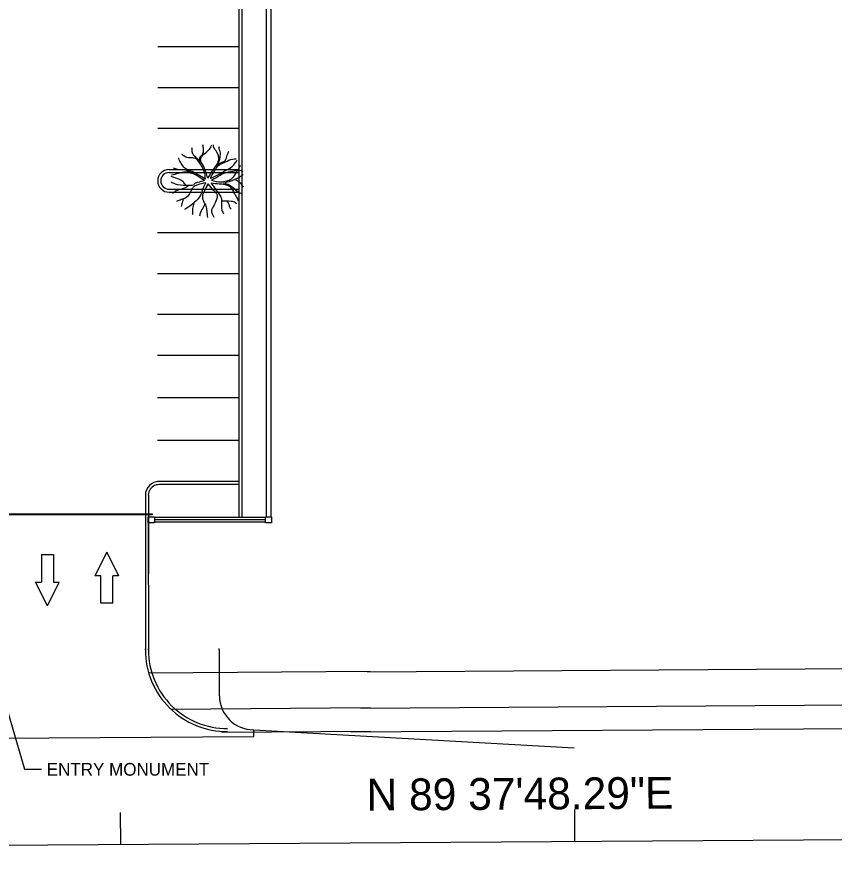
# Model space of a CAD drawing. Extents: x 6711323 to 6714641, y 1869258 to 1871224.
# Drawn here: x 6713129 to 6713309, y 1869589.4 to 1869774.5 of the extents above; entities that cross this region are included whole.
import ezdxf

# ---------------------------------------------------------------- set-up
doc = ezdxf.new("R2010")
doc.units = 0
for name, color, linetype in [('49 Planting', 7, 'Continuous'), ('Curb Gutter (21)', 7, 'Continuous'), ('Exist Utils (5)', 7, 'Continuous'), ('Front Align (17)', 7, 'Continuous'), ('Level 11', 7, 'Continuous'), ('Level 13', 7, 'Continuous'), ('Level 14', 7, 'Continuous'), ('Level 21', 7, 'Continuous'), ('Level 46', 7, 'Continuous'), ('Level 60', 7, 'Continuous'), ('Misc CnstDet(22)', 7, 'Continuous'), ('Nongeo Data(60)', 7, 'Continuous'), ('Profile Grid (9)', 7, 'Continuous'), ('Undefined (Lv19)', 7, 'Continuous'), ('Undefined (Lv26)', 7, 'Continuous')]:
    doc.layers.add(name, color=color, linetype=linetype)

msp = doc.modelspace()

# ---------------------------------------------------------------- linework, layer by layer
at = {"layer": '49 Planting'}
for p, q in [((6713122.22, 1869637.78), (6713130.69, 1869608.81)), ((6713130.69, 1869608.81), (6713134.46, 1869608.82))]:
    msp.add_line(p, q, dxfattribs=at)
at = {"layer": 'Curb Gutter (21)'}
for p, q in [((6713177.99, 1869664.24), (6713177.99, 1869903.09)), ((6713178.66, 1869664.24), (6713178.66, 1869903.12)), ((6713162.53, 1869740.86), (6713177.99, 1869740.86)), ((6713162.53, 1869735.86), (6713177.99, 1869735.86)), ((6713177.99, 1869672.16), (6713160.31, 1869672.16)), ((6713157.31, 1869663.67), (6713157.31, 1869635.09)), ((6713157.96, 1869663.72), (6713157.98, 1869635.09))]:
    msp.add_line(p, q, dxfattribs=at)
for centre, radius, end in [((6713162.53, 1869738.36), 2.5, 270), ((6713160.31, 1869669.16), 3, 180)]:
    msp.add_arc(centre, radius, 90, end, dxfattribs=at)
at = {"layer": 'Exist Utils (5)'}
msp.add_line((6713157.31, 1869669.19), (6713157.31, 1869651.86), dxfattribs=at)
at = {"layer": 'Front Align (17)'}
for p, q in [((6713178.03, 1869767.86), (6713160.03, 1869767.86)), ((6713178.03, 1869758.86), (6713160.03, 1869758.86)), ((6713178.03, 1869749.86), (6713160.03, 1869749.86)), ((6713177.99, 1869726.9), (6713159.99, 1869726.9)), ((6713177.99, 1869717.9), (6713159.99, 1869717.9)), ((6713177.99, 1869708.9), (6713159.99, 1869708.9)), ((6713177.99, 1869699.9), (6713159.99, 1869699.9)), ((6713177.99, 1869690.62), (6713159.99, 1869690.62)), ((6713177.99, 1869681.16), (6713159.99, 1869681.16)), ((6713177.99, 1869681.16), (6713159.99, 1869681.16)), ((6713177.99, 1869672.16), (6713159.99, 1869672.16))]:
    msp.add_line(p, q, dxfattribs=at)
at = {"layer": 'Level 11'}
for p, q in [((6713173.56, 1869635.09), (6713173.56, 1869624.94)), ((6713181.16, 1869617.49), (6713251.7, 1869613.53)), ((6713181.17, 1869615.99), (6713181.16, 1869617.49)), ((6712948.69, 1869614.49), (6713181.17, 1869615.99))]:
    msp.add_line(p, q, dxfattribs=at)
msp.add_arc((6713181.12, 1869624.99), 7.5, 180.3699, 270.2774, dxfattribs=at)
at = {"layer": 'Level 13'}
msp.add_line((6712709.06, 1869589.44), (6713820.2, 1869596.61), dxfattribs=at)
at = {"layer": 'Level 14'}
for points in [[(6713151.79, 1869599.3), (6713151.83, 1869592.3)], [(6713251.78, 1869599.95), (6713251.83, 1869592.95)]]:
    msp.add_lwpolyline(points, dxfattribs=at)
at = {"layer": 'Level 21'}
for p, q in [((6713173.56, 1869635.09), (6713173.56, 1869624.94)), ((6713181.16, 1869617.49), (6713251.7, 1869613.53)), ((6712948.69, 1869614.49), (6713181.17, 1869615.99)), ((6712948.69, 1869614.49), (6713181.17, 1869615.99))]:
    msp.add_line(p, q, dxfattribs=at)
msp.add_arc((6713181.12, 1869624.99), 7.5, 180.3699, 270.2774, dxfattribs=at)
at = {"layer": 'Level 46'}
for p, q in [((6713157.31, 1869635.09), (6713157.31, 1869635.32)), ((6713157.98, 1869635.09), (6713157.98, 1869635.32)), ((6713173.56, 1869635.09), (6713173.56, 1869635.42)), ((6713206.25, 1869630.28), (6713790.23, 1869633.99)), ((6713158.04, 1869630.02), (6713206.81, 1869630.37)), ((6713204.75, 1869622.27), (6713790.23, 1869625.99)), ((6713162.9, 1869622.06), (6713206.87, 1869622.37)), ((6713202.57, 1869617.07), (6713790.35, 1869620.81)), ((6713174.13, 1869616.97), (6713206.9, 1869617.18))]:
    msp.add_line(p, q, dxfattribs=at)
for radius in [18, 18, 17.33]:
    msp.add_arc((6713175.31, 1869635.09), radius, 180, 270.3648, dxfattribs=at)
at = {"layer": 'Level 60'}
msp.add_line((6713181.17, 1869615.99), (6713181.16, 1869617.49), dxfattribs=at)
at = {"layer": 'Misc CnstDet(22)'}
for p in [(6713183.79, 1869663.74), (6713176.47, 1869663.74)]:
    msp.add_line(p, (6713159.3, 1869663.74), dxfattribs=at)
msp.add_lwpolyline([(6713124.96, 1869665.07), (6713158.81, 1869665.07), (6713158.81, 1869664.82), (6713124.96, 1869664.82)], close=True, dxfattribs=at)
msp.add_lwpolyline([(6713124.96, 1869665.07), (6713158.81, 1869665.07), (6713158.81, 1869664.82), (6713124.96, 1869664.82)], close=True, dxfattribs=at)
at = {"layer": 'Nongeo Data(60)'}
for p, q in [((6713183.98, 1869664.41), (6713183.98, 1869902.46)), ((6713184.98, 1869664.41), (6713184.98, 1869902.48))]:
    msp.add_line(p, q, dxfattribs=at)
at = {"layer": 'Profile Grid (9)'}
for points in [[(6713169.36, 1869742.48), (6713168.65, 1869743.32), (6713167.74, 1869744.34), (6713167.61, 1869745.24), (6713167.55, 1869745.6)], [(6713169.23, 1869742.84), (6713169.42, 1869743.62), (6713169.55, 1869743.8), (6713169.94, 1869744.28), (6713170.14, 1869745.3), (6713169.94, 1869746.32)], [(6713171.04, 1869738.94), (6713170.66, 1869740.26), (6713169.94, 1869741.88), (6713169.49, 1869742.78), (6713169.68, 1869743.68), (6713170.2, 1869744.22), (6713171.17, 1869745.06), (6713171.69, 1869745.72), (6713171.95, 1869746.26)], [(6713171.04, 1869738.94), (6713172.28, 1869740.86), (6713173.44, 1869742.84), (6713173.44, 1869743.74), (6713173.05, 1869744.7), (6713172.4, 1869745.72), (6713172.28, 1869746.26)], [(6713173.05, 1869741.7), (6713173.57, 1869742.72), (6713173.77, 1869743.56), (6713173.77, 1869744.82), (6713173.57, 1869745.54), (6713173.64, 1869745.9)], [(6713170.53, 1869738.76), (6713168.4, 1869739.98), (6713166.76, 1869740.78), (6713165.99, 1869741.17), (6713165.21, 1869742.21), (6713164.69, 1869743.25), (6713164.69, 1869743.41)], [(6713170.53, 1869738.76), (6713170.27, 1869740.44), (6713169.62, 1869741.76), (6713168.84, 1869742.84), (6713168.32, 1869743.32), (6713168, 1869743.38), (6713167.16, 1869743.44), (6713166.44, 1869743.5), (6713165.6, 1869743.98), (6713165.34, 1869744.16)], [(6713171.63, 1869738.94), (6713172.73, 1869740.92), (6713173.25, 1869741.58), (6713174.02, 1869742.12), (6713175.32, 1869742.72), (6713176.94, 1869743.2), (6713177.33, 1869743.2)], [(6713173.05, 1869741.7), (6713174.02, 1869742.42), (6713174.74, 1869742.72), (6713175.06, 1869743.14), (6713175.45, 1869744.28), (6713175.71, 1869744.88)], [(6713171.63, 1869738.94), (6713174.01, 1869740.06), (6713175.05, 1869740.7), (6713175.82, 1869741.09), (6713177.03, 1869742.21), (6713177.55, 1869742.93)], [(6713171.85, 1869738.54), (6713174.01, 1869738.14), (6713175.22, 1869738.38), (6713176.25, 1869738.78), (6713177.2, 1869739.98), (6713177.89, 1869741.09), (6713178.24, 1869741.81)], [(6713167.54, 1869739.98), (6713166.24, 1869740.3), (6713164.52, 1869739.98), (6713163.05, 1869739.58)], [(6713170.3, 1869738.46), (6713168.92, 1869739.34), (6713167.19, 1869740.3), (6713165.9, 1869740.78), (6713164.43, 1869740.85), (6713163.48, 1869741.17)], [(6713171.85, 1869738.54), (6713173.75, 1869739.58), (6713174.87, 1869740.14), (6713175.91, 1869740.38), (6713176.86, 1869740.54), (6713178.41, 1869740.62), (6713178.76, 1869740.46)], [(6713174.53, 1869737.9), (6713176.17, 1869738.38), (6713177.2, 1869738.78), (6713178.24, 1869739.34), (6713178.84, 1869739.74)], [(6713166.24, 1869737.42), (6713165.64, 1869738.14), (6713163.83, 1869739.02), (6713162.97, 1869739.34)], [(6713170.3, 1869738.46), (6713168.75, 1869737.98), (6713168.14, 1869737.74), (6713167.88, 1869737.42), (6713167.37, 1869737.34), (6713166.16, 1869737.34), (6713163.91, 1869737.66), (6713162.97, 1869738.06)], [(6713170.56, 1869737.9), (6713168.83, 1869737.5), (6713168.14, 1869737.18), (6713167.62, 1869736.7), (6713167.19, 1869735.82), (6713166.33, 1869734.71), (6713165.21, 1869734.23), (6713164.17, 1869733.83)], [(6713170.56, 1869737.9), (6713169.95, 1869736.62), (6713169.44, 1869735.19), (6713168.49, 1869733.99), (6713167.02, 1869732.71), (6713165.9, 1869732.07)], [(6713171.08, 1869737.74), (6713170.3, 1869736.14), (6713169.87, 1869734.95), (6713170.13, 1869733.83), (6713170.65, 1869732.79), (6713170.82, 1869731.75), (6713170.99, 1869730.32)], [(6713171.08, 1869737.74), (6713172.28, 1869736.3), (6713172.89, 1869735.67), (6713173.15, 1869735.11), (6713172.97, 1869734.23), (6713172.37, 1869732.87), (6713171.85, 1869731.67), (6713172.11, 1869730.95), (6713172.37, 1869730.4)], [(6713171.77, 1869737.9), (6713173.58, 1869737.74), (6713174.87, 1869737.58), (6713175.82, 1869737.18), (6713176.43, 1869736.46), (6713176.94, 1869735.51), (6713177.38, 1869734.79), (6713177.72, 1869733.99)], [(6713171.77, 1869737.9), (6713172.28, 1869737.18), (6713173.32, 1869735.74), (6713173.92, 1869734.87), (6713174.1, 1869733.83), (6713174.18, 1869731.91), (6713174.53, 1869731.11)], [(6713174.53, 1869737.9), (6713175.74, 1869737.5), (6713176.68, 1869736.86), (6713177.72, 1869735.98), (6713178.5, 1869735.51)], [(6713177.2, 1869738.62), (6713177.72, 1869738.3), (6713178.58, 1869737.42), (6713178.84, 1869736.94)], [(6713166.76, 1869737.18), (6713165.3, 1869736.54), (6713164.09, 1869736.14), (6713163.31, 1869735.59)], [(6713165.73, 1869734.47), (6713165.47, 1869733.83), (6713165.21, 1869732.71)], [(6713174.1, 1869733.99), (6713176.17, 1869733.91), (6713177.12, 1869733.59), (6713177.38, 1869733.35)], [(6713175.22, 1869733.91), (6713175.65, 1869733.35), (6713175.82, 1869732.63), (6713176.17, 1869732.15)], [(6713167.97, 1869733.43), (6713167.71, 1869732.31), (6713167.71, 1869730.95)], [(6713170.39, 1869733.27), (6713170.13, 1869732.63), (6713169.44, 1869731.43), (6713169.26, 1869730.56)]]:
    msp.add_spline(points, degree=3, dxfattribs=at)
at = {"layer": 'Undefined (Lv19)'}
for p, q in [((6713162.53, 1869740.2), (6713177.99, 1869740.2)), ((6713162.53, 1869736.53), (6713177.99, 1869736.53)), ((6713177.99, 1869671.49), (6713160.31, 1869671.49)), ((6713157.98, 1869669.12), (6713158.2, 1869670.16)), ((6713157.98, 1869669.12), (6713157.98, 1869651.86)), ((6713148.8, 1869656.62), (6713146.2, 1869651.42)), ((6713148.8, 1869656.62), (6713151.41, 1869651.42)), ((6713134.45, 1869656.06), (6713137.05, 1869656.06)), ((6713134.45, 1869656.06), (6713134.45, 1869649.99)), ((6713137.05, 1869656.06), (6713137.05, 1869649.99)), ((6713147.5, 1869651.42), (6713146.2, 1869651.42)), ((6713147.5, 1869645.35), (6713147.5, 1869651.42)), ((6713150.11, 1869645.35), (6713150.11, 1869651.42)), ((6713151.41, 1869651.42), (6713150.11, 1869651.42)), ((6713133.15, 1869649.99), (6713134.45, 1869649.99)), ((6713135.75, 1869644.78), (6713133.15, 1869649.99)), ((6713135.75, 1869644.78), (6713138.36, 1869649.99)), ((6713137.05, 1869649.99), (6713138.36, 1869649.99)), ((6713150.11, 1869645.35), (6713147.5, 1869645.35))]:
    msp.add_line(p, q, dxfattribs=at)
for centre, radius, end in [((6713162.53, 1869738.36), 1.83, 270), ((6713160.31, 1869669.16), 2.33, 154.6231)]:
    msp.add_arc(centre, radius, 90, end, dxfattribs=at)
at = {"layer": 'Undefined (Lv26)'}
for p, q in [((6713157.96, 1869663.06), (6713157.96, 1869664.39)), ((6713157.96, 1869664.39), (6713159.3, 1869664.39)), ((6713157.96, 1869663.06), (6713157.96, 1869664.39)), ((6713157.96, 1869664.39), (6713159.3, 1869664.39)), ((6713159.3, 1869664.39), (6713159.3, 1869663.06)), ((6713159.3, 1869664.39), (6713159.3, 1869663.06)), ((6713176.47, 1869664.24), (6713159.3, 1869664.24)), ((6713183.79, 1869664.24), (6713159.3, 1869664.24)), ((6713183.79, 1869663.06), (6713183.79, 1869664.39)), ((6713183.79, 1869664.39), (6713185.12, 1869664.39)), ((6713185.12, 1869664.39), (6713185.12, 1869663.06)), ((6713159.3, 1869663.06), (6713157.96, 1869663.06)), ((6713159.3, 1869663.06), (6713157.96, 1869663.06)), ((6713176.47, 1869663.24), (6713159.3, 1869663.24)), ((6713183.79, 1869663.24), (6713159.3, 1869663.24)), ((6713185.12, 1869663.06), (6713183.79, 1869663.06))]:
    msp.add_line(p, q, dxfattribs=at)

# ---------------------------------------------------------------- texts
at = {"layer": '49 Planting'}
msp.add_text('ENTRY MONUMENT', height=2.8, rotation=0, dxfattribs=at).set_placement((6713135.59, 1869607.39))
at = {"layer": 'Level 14'}
msp.add_text('N 89 37\'48.29"E', height=7, rotation=0.3651, dxfattribs=at).set_placement((6713206.03, 1869599.7))

doc.saveas('drawing.dxf')
